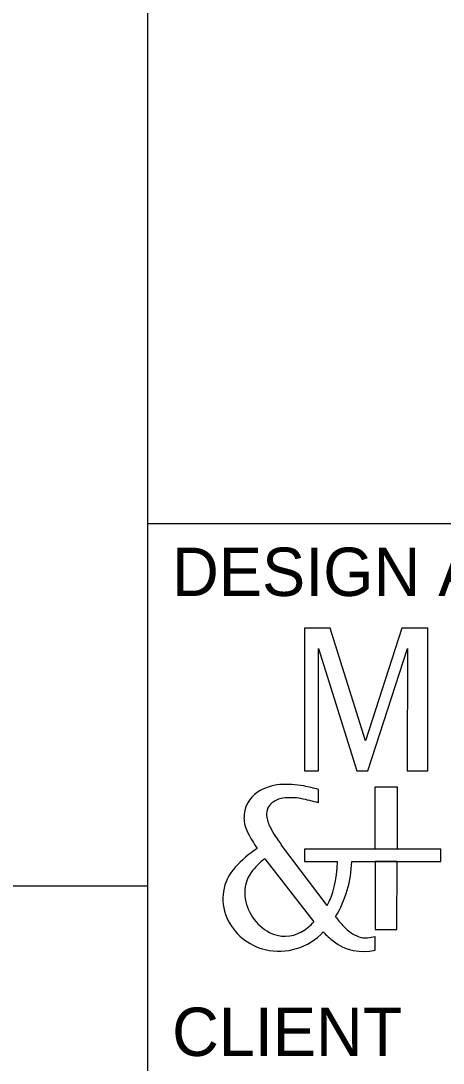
# Model space of a CAD drawing. Extents: x -7.3 to 34, y 0 to 22.
# Drawn here: x 31.738 to 32.61, y 3.384 to 5.54 of the extents above; entities that cross this region are included whole.
import ezdxf

# ---------------------------------------------------------------- set-up
doc = ezdxf.new("R2010")
doc.units = 0
for name, color, linetype in [('SH_Border', 7, 'Continuous'), ('SH_Data', 7, 'Continuous'), ('SH_Text', 7, 'Continuous')]:
    doc.layers.add(name, color=color, linetype=linetype)

msp = doc.modelspace()

# ---------------------------------------------------------------- linework, layer by layer
at = {"layer": 'SH_Border'}
for p, q in [((32, 0.5), (32, 21.5)), ((32, 4.5), (33.5, 4.5))]:
    msp.add_line(p, q, dxfattribs=at)
at = {"layer": 'SH_Data'}
for p, q in [((32.3525, 3.922), (32.3525, 3.9497)), ((32.4696, 3.8261), (32.4697, 3.9552)), ((32.4697, 3.9552), (32.5147, 3.9552)), ((32.5147, 3.9552), (32.5146, 3.8261)), ((32.37, 3.7101), (32.2762, 3.8349)), ((32.2416, 3.8065), (32.3429, 3.6759)), ((32.4696, 3.8006), (32.4696, 3.6605)), ((32.5146, 3.8006), (32.4696, 3.8006)), ((32.5145, 3.6605), (32.5146, 3.8006)), ((32.1797, 3.7884), (32.18, 3.7887)), ((32, 3.75), (29.2, 3.75)), ((32, 0.5), (32, 3.75)), ((32.4694, 3.6176), (32.4695, 3.646)), ((32.4696, 3.6605), (32.5145, 3.6605))]:
    msp.add_line(p, q, dxfattribs=at)
msp.add_lwpolyline([(32.3526, 3.9885), (32.3527, 4.2417), (32.4317, 3.9885), (32.4542, 3.9885), (32.536, 4.2417), (32.5359, 3.9885), (32.5784, 3.9885), (32.5785, 4.2831), (32.5246, 4.2831), (32.4495, 4.0504), (32.3765, 4.2832), (32.3235, 4.2832), (32.3234, 3.9886)], close=True, dxfattribs=at)
msp.add_lwpolyline([(32.3526, 3.9885), (32.3527, 4.2417), (32.4317, 3.9885), (32.4542, 3.9885), (32.536, 4.2417), (32.5359, 3.9885), (32.5784, 3.9885), (32.5785, 4.2831), (32.5246, 4.2831), (32.4495, 4.0504), (32.3765, 4.2832), (32.3235, 4.2832), (32.3234, 3.9886)], close=True, dxfattribs=at)
msp.add_lwpolyline([(32.4211, 3.8006), (32.6049, 3.8006), (32.6049, 3.8261), (32.3233, 3.8261), (32.3233, 3.8007), (32.3916, 3.8006)], dxfattribs=at)
for centre, radius, start, end in [((32.2803, 3.862), 0.0981, 94.5206, 123.1061), ((32.2871, 3.7753), 0.1851, 79.0563, 94.5206), ((32.2546, 3.6069), 0.3566, 74.0516, 79.0563), ((32.2606, 3.8922), 0.062, 123.1061, 181.2152), ((32.2855, 3.8851), 0.0471, 98.3723, 128.329), ((32.2951, 3.8196), 0.1132, 79.2666, 98.3723), ((32.2495, 3.579), 0.3581, 73.2803, 79.2666), ((32.2746, 3.8989), 0.0295, 128.329, 186.0821), ((32.2669, 3.8924), 0.0684, 181.2152, 207.1091), ((32.3115, 3.9028), 0.0666, 186.0821, 208.5769), ((32.517, 4.0204), 0.3493, 207.1091, 213.4656), ((32.5116, 4.0118), 0.2945, 208.5769, 216.933), ((32.3628, 3.6213), 0.2479, 123.6, 137.6035), ((32.3108, 3.7092), 0.1194, 125.3927, 144.9042), ((32.1831, 3.8084), 0.2382, 329.2356, 358.1314), ((32.2512, 3.7236), 0.0964, 137.6035, 203.9313), ((32.2717, 3.7366), 0.0717, 144.9042, 185.7554), ((32.2959, 3.7391), 0.096, 185.7554, 242.1528), ((32.5828, 3.8332), 0.2441, 216.933, 222.2898), ((32.2691, 3.7316), 0.116, 203.9313, 256.6813), ((32.2633, 3.7491), 0.1081, 299.979, 317.3992), ((32.4823, 3.7418), 0.1082, 222.2898, 236.5762), ((32.271, 3.7399), 0.1246, 256.6813, 317.1089), ((32.2831, 3.7148), 0.0685, 242.1528, 299.979), ((32.487, 3.7702), 0.1697, 222.685, 232.3525), ((32.453, 3.6975), 0.0551, 236.5762, 256.9728), ((32.4497, 3.6832), 0.0405, 256.9728, 275.0638), ((32.446, 3.7257), 0.0831, 275.0638, 286.4619), ((32.4453, 3.7161), 0.1014, 232.3525, 283.7629)]:
    msp.add_arc(centre, radius, start, end, dxfattribs=at)
msp.add_ellipse((32.351, 3.8018), major_axis=(-0.0031, -0.1077), ratio=0.377453, start_param=0.562501, end_param=1.570796, dxfattribs=at)

# ---------------------------------------------------------------- texts
msp.add_text('DESIGN AGENCY', height=0.1, dxfattribs=at).set_placement((32.05, 4.35))
at = {"layer": 'SH_Text'}
msp.add_text('CLIENT', height=0.1, dxfattribs=at).set_placement((32.05, 3.3986))

doc.saveas('drawing.dxf')
